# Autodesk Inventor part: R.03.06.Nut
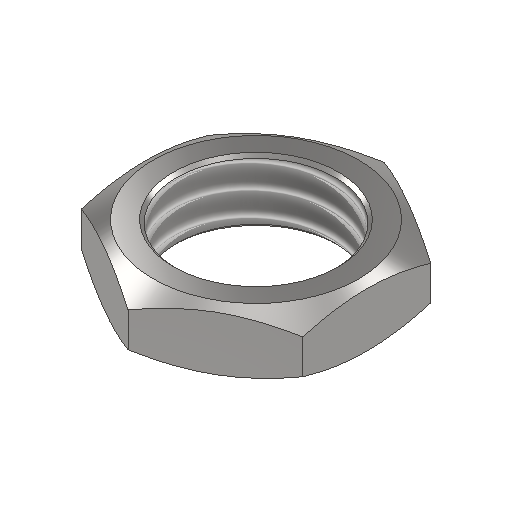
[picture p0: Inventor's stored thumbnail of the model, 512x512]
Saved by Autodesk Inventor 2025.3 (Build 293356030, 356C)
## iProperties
Created: 2021-02
Part Number: R.03.06.Nut
Material: Stainless Steel
Document SubType Name: Modeling
Designer: Михальчик
Density: 8 g/cm^3
Appearance: Semi-Polished
Author: Михальчик
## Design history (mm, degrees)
sketch "Sketch1"
  geometry: L1 (0, 0)-(0, 19.932); L2 (5, 0)-(8.5, 0); L3 (8.5, 0)-(8.5, 4); L4 (8.5, 4)-(5, 4); L5 (5, 4)-(5, 0); L6 (6.5, 4)-(8.5, 2.845); L7 (8.5, 1.155)-(6.5, 0)
  constraints: 14 end point, 5 point on line, 2 parallel, 1 equal length, 1 horizontal, 1 perpendicular, 1 vertical
  dimensions: "d0" = 10 diameter of L5 L1; "d1" = 17 diameter of L3 L1; "d2" = 4 distance of L2.end L3.end; "d3" = 150 deg angle of L4 L6; "d4" = 13 diameter of L6.start L1; "d5" = 30 deg angle of L2 L7
revolve "Revolution1" sketch "Sketch1" stored, may be unused: angle "d6" = 90 deg
thread "Thread1" dims "d7" = 4, "d8" = 0
chamfer "Chamfer1" distance "d9" = 0.2; stored, may be unused: second distance "d10" = 2, angle "d11" = 45 deg
sketch "Sketch2"
  geometry: L1 (0, 8.083)-(7, 4.041); L2 (7, 4.041)-(7, -4.041); L3 (7, -4.041)-(0, -8.083); L4 (0, -8.083)-(-7, -4.041); L5 (-7, -4.041)-(-7, 4.041); L6 (-7, 4.041)-(0, 8.083); C1 r 8.5 at (0, 0); 2 further points
  constraints: 12 end point, 1 centre point, 1 coincident, 13 other
  dimensions: "d12" = 14 distance between parallel lines of L2 L5
extrude "Extrusion1" cut sketch "Sketch2" distance "d13" = 10; taper "d14" = 0 deg
body "Solid1"
